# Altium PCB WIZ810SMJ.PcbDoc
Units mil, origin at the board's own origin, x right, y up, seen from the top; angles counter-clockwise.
Board outline 984.25 x 2047.24 mil, 2 copper layers (Top Layer, Bottom Layer); 47 components, 44 nets, 208 pads, 90 vias.
Unrouted connection lines stored in the file: 4.
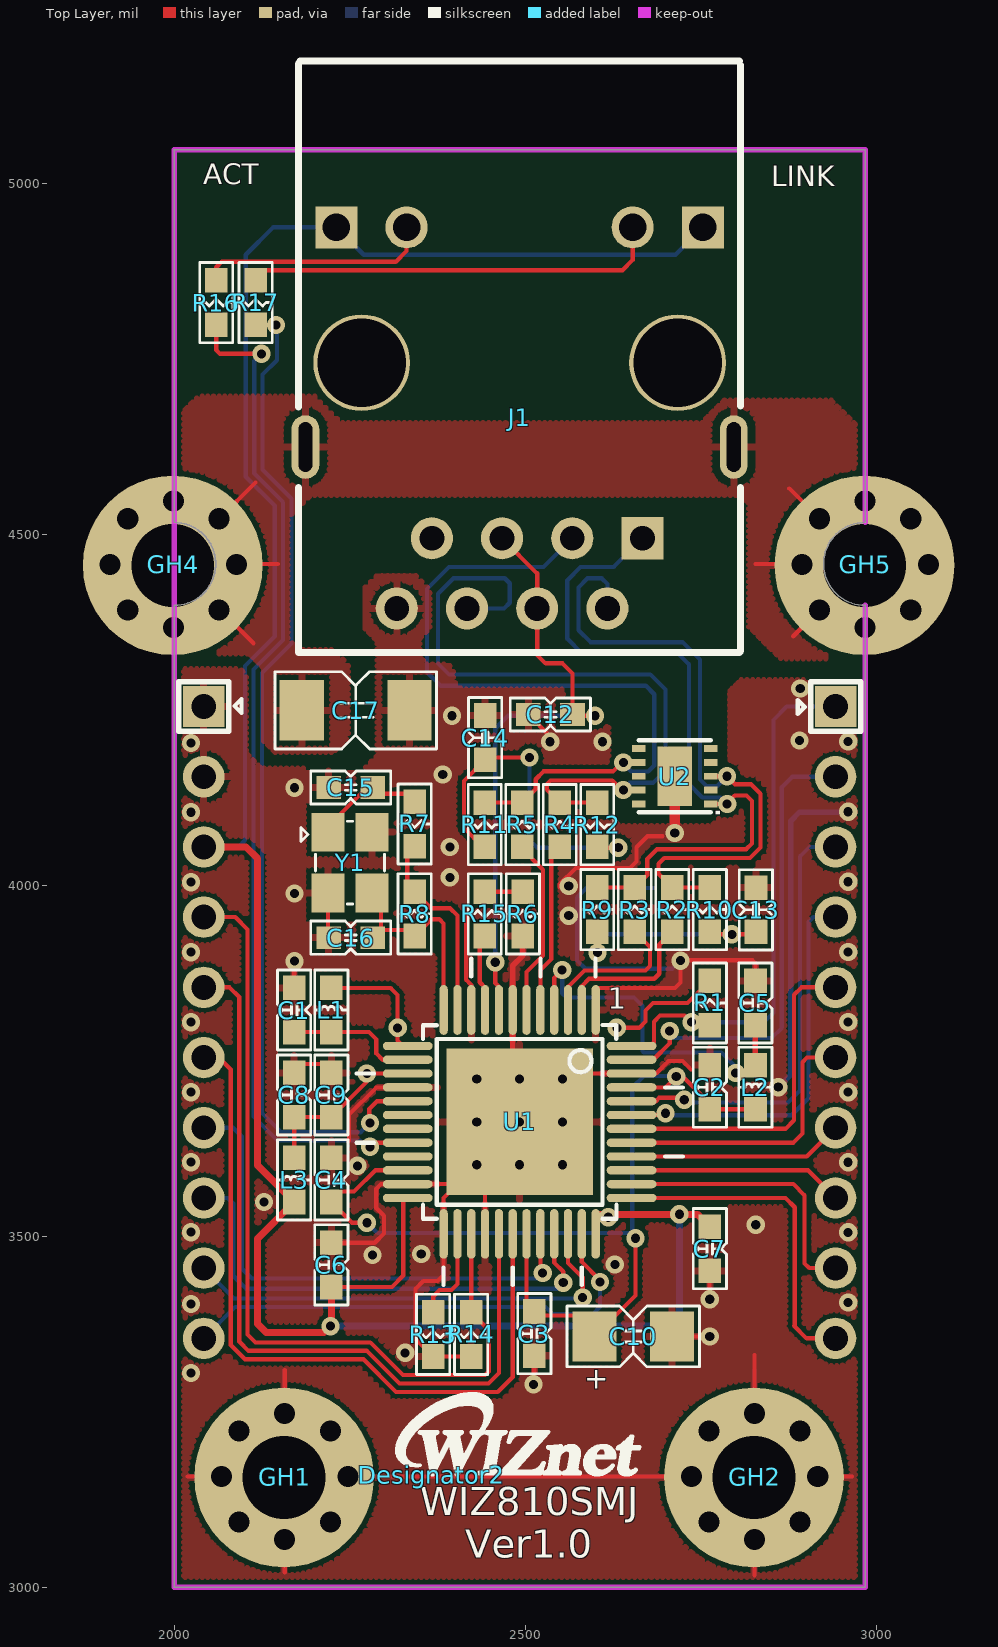
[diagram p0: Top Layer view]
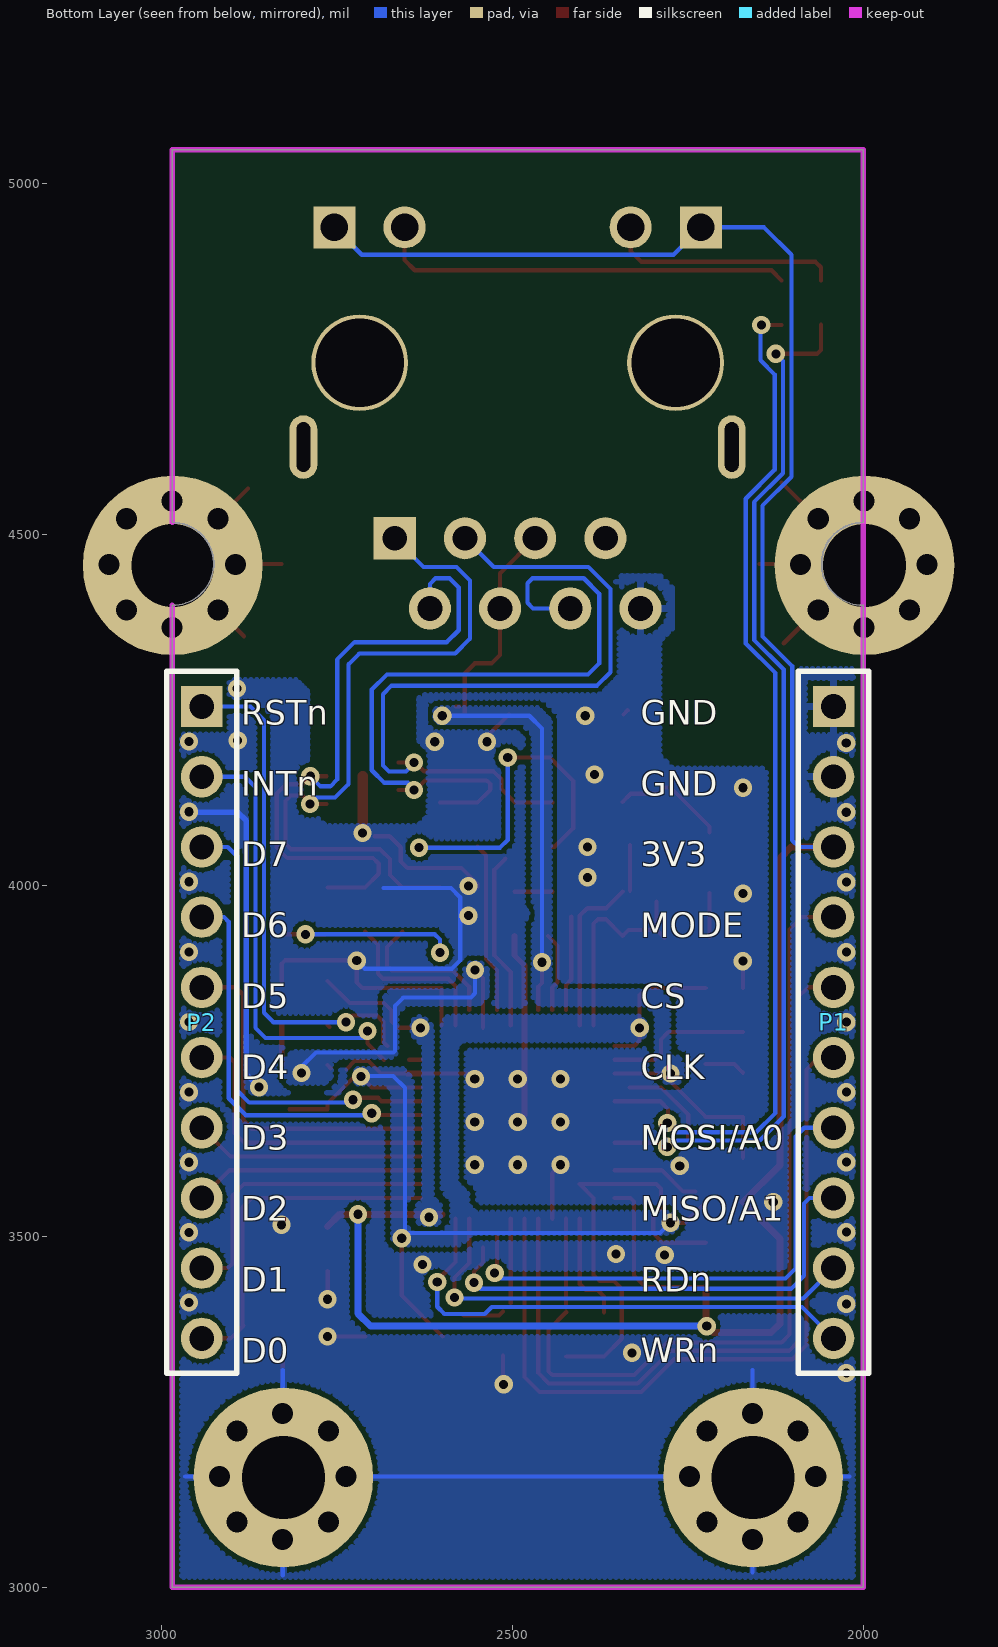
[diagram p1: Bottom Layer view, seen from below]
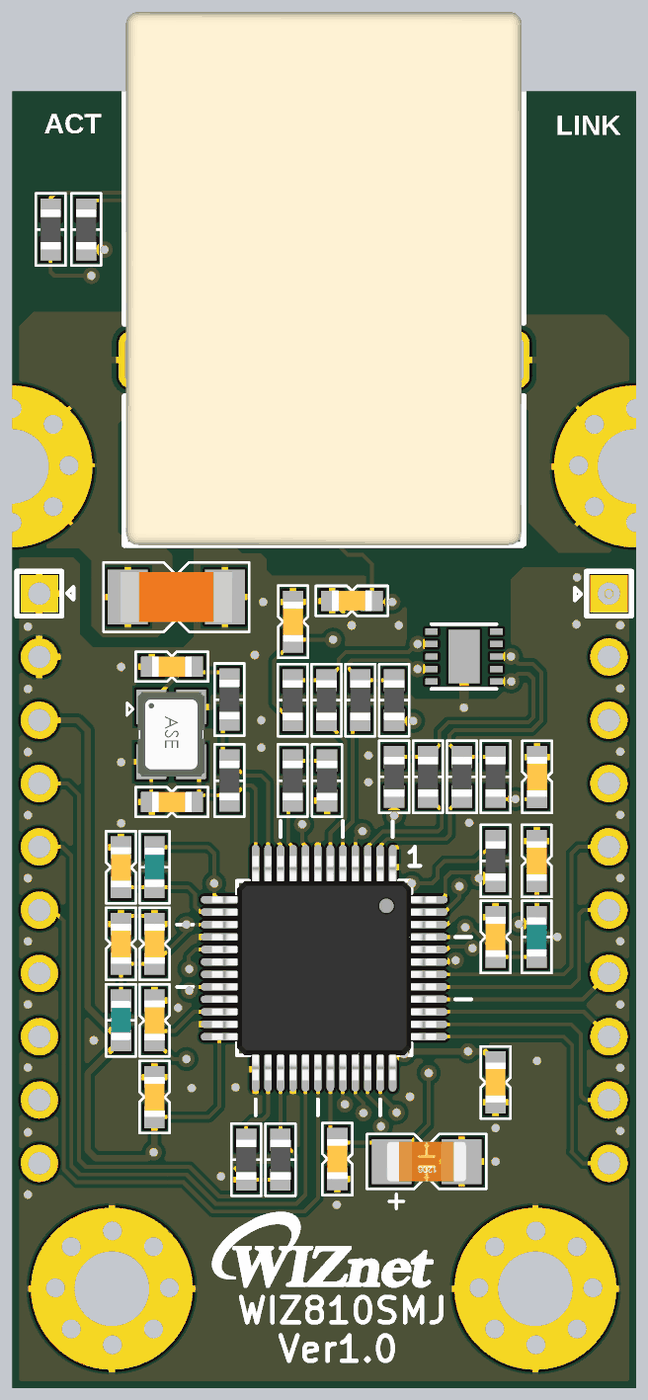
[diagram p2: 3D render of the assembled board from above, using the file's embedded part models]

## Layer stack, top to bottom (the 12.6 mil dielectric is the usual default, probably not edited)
Top Layer: signal copper 1.4
Dielectric: core 12.6, FR-4, Dk 4.8
Bottom Layer: signal copper 1.4

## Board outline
2000,3000 2000,4398.43 ccw(c2000,4457.48) 2000,4516.53 2000,5047.24 2984.25,5047.24 2984.25,4516.53 ccw(c2984.25,4457.48) 2984.25,4398.43 2984.25,3000

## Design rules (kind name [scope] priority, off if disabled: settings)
Clearance [All] p1: gap=6
DiffPairsRouting [All] p1: maxlimit=10 minlimit=10 mostfreqgap=10 maxuncoupledlength=500
FabricationTestPointUsage TestPointUsage [All] p1: valid=0 allowmultiple=FALSE
FabricationTestpoint Testpoint [All] p1: side=3 testpointundercomponent=TRUE minsize=40 maxsize=100 preferedsize=60 minholesize=0 maxholesize=40 preferedholesize=32 testpointgrid=1 allowsidetop=TRUE allowsidebottom=TRUE usegrid=TRUE gridtolerance=0.01
PlaneConnect [All] p1: planeconnectstyle=Relief reliefexpansion=20 reliefentries=4 reliefconductorwidth=10 reliefairgap=6
PolygonConnect PolygonConnect_1 [IsVia] p1: connectstyle=Direct reliefconductorwidth=10 reliefentries=4 polygonreliefangle="90 Angle" airgapwidth=10
PolygonConnect [All] p2: connectstyle=Relief reliefconductorwidth=10 reliefentries=4 polygonreliefangle="90 Angle" airgapwidth=7
RoutingVias [All] p1: holewidth=23.62 width=39.37 viastyle="Through Hole" minholewidth=13 minwidth=26 maxholewidth=28 maxwidth=50
SilkToSolderMaskClearance SilkscreenOverComponentPads [IsPad] p1: minsilkscreentomaskgap=10 clearancetoexposedcopper=TRUE
SolderMaskExpansion [All] p1: expansion=4
Width [All] p1: maxlimit=10 minlimit=6 preferedwidth=6
23 further rules are at their usual default settings.

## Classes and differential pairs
differential pair TXO: +TXO_P -TXO_N
differential pair RXO: +RXO_P -RXO_N

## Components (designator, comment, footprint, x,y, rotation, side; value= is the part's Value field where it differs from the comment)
C1 "100nF" 0603-C 2170.98,3822 r270 top
C2 "100nF" 0603-C 2763,3712 r270 top
C3 "100nF" 0603-C 2513,3361 r90 top
C4 "100nF" 0603-C 2224,3580 r270 top
C5 "100nF" 0603-C 2828,3832 r270 top
C6 "100nF" 0603-C 2224,3459 r270 top
C7 "100nF" 0603-C 2763,3482 r90 top
C8 "100nF" 0603-C 2170.98,3701 r270 top
C9 "100nF" 0603-C 2224,3701 r270 top
C10 "3.3uF/3216" CAP-1206 2654,3357 r180 top
C12 "1uF" 0603-C 2536,4243 r0 top
C13 "100nF" 0603-C 2828.74,3964.76 r270 top
C14 "100nF" 0603-C 2443,4210 r270 top
C15 "8pF" 0603-C 2251.5,4139 r0 top
C16 "8pF" 0603-C 2251.5,3925 r0 top
C17 "1nF/2kV" CAP-1808 2258.58,4248.98 r0 top
Designator2 "Comment" LOGO-WIZNET(SMALL) 2367.13,3160 r0 top
GH1 "CON8" 定位孔（带小孔） 2157.48,3157.48 r0 top
GH2 "CON8" 定位孔（带小孔） 2826.77,3157.48 r0 top locked
GH4 "CON8" 定位孔（带小孔） 1998.87,4456.8 r0 top
GH5 "CON8" 定位孔（带小孔） 2984.25,4456.8 r0 top
J1 "HRW5500RE" RJ-45(HRW5500RE) 2492.13,4744.04 r180 top locked
L1 "HH-1M1608-121JT" 0603-L 2224,3822 r90 top
L2 "HH-1M1608-121JT" 0603-L 2828,3712 r90 top
L3 "HH-1M1608-121JT" 0603-L 2170.98,3580 r90 top
P1 "Header 10" HDR1X10 2042.13,4254.33 r270 bottom locked
P2 "Header 10" HDR1X10 2942.13,4254.33 r270 bottom
R1 "4.7k" 0603-R 2763,3832 r90 top
R2 "3.3R" 0603-R 2709.57,3965 r90 top
R3 "3.3R" 0603-R 2656.14,3965 r90 top
R4 "3.3R" 0603-R 2549.29,4086 r90 top
R5 "3.3R" 0603-R 2495.86,4086 r90 top
R6 "300/1%" RES-0603 2496.65,3959 r90 top
R7 "0R" 0603-R 2342.5,4087 r270 top
R8 "1M" 0603-R 2342.5,3959 r90 top
R9 "49.9R" 0603-R 2602.71,3965 r90 top
R10 "49.9R" 0603-R 2763,3965 r90 top
R11 "49.9R" 0603-R 2442.43,4086 r90 top
R12 "49.9R" 0603-R 2602.71,4086 r90 top
R13 "10K" 0603-R 2369,3360 r90 top
R14 "10K" 0603-R 2423,3360 r90 top
R15 "12K/1%" RES-0603 2442.43,3959 r270 top
R16 "1K" 0603-R 2059.97,4829.76 r90 top
R17 "1K" 0603-R 2116.04,4829.76 r90 top
U1 "W5100S" "WIZNET W5100S QFN&TQFP" 2492.13,3662.6 r270 top locked
U2 "RClamp3304N" DFN-10 2713.08,4155.01 r90 top
Y1 "25MHz" OSC-82J0626 2250.5,4032 r270 top

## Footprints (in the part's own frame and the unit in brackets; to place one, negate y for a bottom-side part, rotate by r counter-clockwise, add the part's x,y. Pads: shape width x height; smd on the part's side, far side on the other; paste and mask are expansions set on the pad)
0603-C [mm]
  rect 0.89x0.82 smd: 1(-0.8,0) 2(0.8,0)
  silkscreen extent -1.45,-0.6 1.45,0.6, body extent -0.93,-0.41 0.93,0.41, height 0.81
0603-L [mm]
  rect 0.89x0.82 smd: 1(-0.8,0) 2(0.8,0)
  silkscreen extent -1.45,-0.6 1.45,0.6, body extent -0.8,-0.4 0.8,0.4, height 0.95
0603-R [mm]
  rect 0.89x0.82 smd: 1(-0.8,0) 2(0.8,0)
  silkscreen extent -1.45,-0.6 1.45,0.6, body extent -0.82,-0.41 0.82,0.41, height 0.46
CAP-1206 [mm]
  rect 1.6x1.8 smd: 1(-1.4,0) 2(1.4,0)
  silkscreen extent -2.4,-1.1 2.4,1.1, body extent -1.6,-0.8 1.6,0.8, height 1
CAP-1808 [mm]
  rect 1.6x2.2 smd: 1(-1.95,0) 2(1.95,0)
  silkscreen extent -2.92,-1.4 2.92,1.4, body extent -2.25,-1.02 2.25,1.01, height 2
DFN-10 [mm] "DFN-10"
  rect 0.25x0.5 smd: 1(-1,-1.3) 2(-0.5,-1.3) 3(0,-1.3) 4(0.5,-1.3) 5(1,-1.3) 6(1,1.3) 7(0.5,1.3) 8(0,1.3) 9(-0.5,1.3) 10(-1,1.3)
  rect 2.15x1.26 smd: 11(0,0)
  silkscreen extent -1.3,-1.3 1.3,1.3
HDR1X10 [mm] "Connector; Header; 10 Position"
  rect 1.5x1.5 hole 0.9: 1(0,0)
  round 1.5 hole 0.9: 2(2.54,0) 3(5.08,0) 4(7.62,0) 5(10.16,0) 6(12.7,0) 7(15.24,0) 8(17.78,0) 9(20.32,0) 10(22.86,0)
  silkscreen extent -1.27,-1.27 24.13,1.27
LOGO-WIZNET(SMALL) [mil]
  silkscreen extent -50,0 296,115
OSC-82J0626 [mm]
  rect 1.4x1.2 smd: 1(-1.1,-0.8) 2(1.1,-0.8) 3(1.1,0.8) 4(-1.1,0.8)
  silkscreen extent -1.5,-1.78 1.5,1.25, body extent -1.7,-1.35 1.7,1.35, height 1.06
RES-0603 [mm]
  rect 0.89x0.82 smd: 1(-0.8,0) 2(0.8,0)
  silkscreen extent -1.45,-0.6 1.45,0.6, body extent -0.82,-0.41 0.82,0.41, height 0.46
RJ-45(HRW5500RE) [mm] "RJ-45(HRW5500RE)"
  rect 1.524x1.524 hole 0.9: 1(-4.445,6.35)
  round 1.524 hole 0.9: 2(-3.175,8.89) 3(-1.905,6.35) 4(-0.635,8.89) 5(0.635,6.35) 6(1.905,8.89) 7(3.175,6.35) 8(4.445,8.89)
  rect 1.524x1.524 hole 1: 9(-6.63,-4.9) 12(6.63,-4.9)
  round 1.524 hole 1: 10(-4.09,-4.9) 11(4.09,-4.9)
  oval 1x2.3 hole 0.5 slot 1.8 at 90 deg: 13(-7.75,3.05) 14(7.75,3.05)
  round 3.5 hole 3.2: ""(-5.715,0) ""(5.715,0)
  silkscreen extent -8,-10.92 8,10.48, body extent -7.92,-10.9 7.96,10.5, height 13.55
"WIZNET W5100S QFN&TQFP" [mm] "WIZNET W5100S QFN&TQFP"
  rect 5.3x5.3 smd: 0(0,0)
  oval 1.8x0.3 smd: 1(-4.05,2.75) 2(-4.05,2.25) 3(-4.05,1.75) 4(-4.05,1.25) 5(-4.05,0.75) 6(-4.05,0.25) 7(-4.05,-0.25) 8(-4.05,-0.75) 9(-4.05,-1.25) 10(-4.05,-1.75) 11(-4.05,-2.25) 12(-4.05,-2.75) 25(4.05,-2.75) 26(4.05,-2.25) 27(4.05,-1.75) 28(4.05,-1.25) 29(4.05,-0.75) 30(4.05,-0.25) 31(4.05,0.25) 32(4.05,0.75) 33(4.05,1.25) 34(4.05,1.75) 35(4.05,2.25) 36(4.05,2.75)
  oval 0.3x1.8 smd: 13(-2.75,-4.05) 14(-2.25,-4.05) 15(-1.75,-4.05) 16(-1.25,-4.05) 17(-0.75,-4.05) 18(-0.25,-4.05) 19(0.25,-4.05) 20(0.75,-4.05) 21(1.25,-4.05) 22(1.75,-4.05) 23(2.25,-4.05) 24(2.75,-4.05) 37(2.75,4.05) 38(2.25,4.05) 39(1.75,4.05) 40(1.25,4.05) 41(0.75,4.05) 42(0.25,4.05) 43(-0.25,4.05) 44(-0.75,4.05) 45(-1.25,4.05) 46(-1.75,4.05) 47(-2.25,4.05) 48(-2.75,4.05)
  silkscreen extent -5.9,-5.9 5.9,5.9, body extent -4.5,-4.5 4.5,4.5, height 1.5
定位孔（带小孔） [mil] "定位孔（带小孔）"
  round 255.91 hole 118.11: 1(-0.86,-1.38)
  round 60 hole 30: 1(0,90) 2(0,-90) 3(-90,0) 4(90,0) 5(-65,65) 6(65,65) 7(-65,-65) 8(65,-65)

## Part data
C1 C2 C3 C4 C5 C6 C7 C8 C9 C12 C13 C14 C15 C16: library part CAP-0603, "Ceramic CAP 0603(1608)"
C10: library part CAP-1206, "Ceramic CAP 1206(3216)"
C17: library part CAP-1808, "Ceramic CAP 1808(4520)"
J1: library part 57-00013QL11-1
L1 L2 L3: library part IND-0603, "Inductor 0603(1608)"
P1 P2: "Header, 10-Pin"
R1 R2 R3 R4 R5 R6 R7 R8 R9 R10 R11 R12 R13 R14 R15 R16 R17: library part RES-0603, "RES0603"
U1: "WIZnet Hardwired TCP/IP Chip"
U2: "Ethernet 3.3V TVS diode, Semtech, SLP2626P10"
Y1: library part OSC-82J0626-25MHz, "X-tal 25MHz,3.2x2.5 SMD, CL=18pF"

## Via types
v1: diameter 26, hole 13, Top Layer to Bottom Layer, tented both sides, 90 vias

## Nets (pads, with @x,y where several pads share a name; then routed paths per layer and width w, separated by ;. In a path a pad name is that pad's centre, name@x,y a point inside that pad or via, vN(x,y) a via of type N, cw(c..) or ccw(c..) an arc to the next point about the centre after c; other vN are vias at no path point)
1V2A: C5.2 L2.2 U1.4 | length 543.8
  Top Layer w6: U1.4@2541.34,3796.73 U1.4@2541.34,3851.61 ; U1.4 2541.34,3867.58 v1(2552.73,3878.97)
  Top Layer w7.87: L2.2 C5.2
  Bottom Layer w6: v1(2552.73,3878.97) 2552.73,3845.9 2558.63,3840 2654.96,3840 2667,3827.96 2667,3763.46 2668.85,3761.61 2779.43,3761.61 2799.82,3741.22 v1(2799.82,3732.2)
1V2D: C2.2 C3.2 C4.2 C10.2 L1.2 L2.1 U1.13 U1.22 U1.31 U1.45 | length 1627.5
  Top Layer w6: C4.2 2253.5,3519 v1(2274.5,3519) v1@2276,3520.5 ; L1.2 2308.41,3853.5 2318.33,3843.58 2318.33,3778.59 2326.05,3770.87 U1.13@2354.33,3770.87 ; C4.2@2238.83,3563.34 2256.34,3563.34 2286.7,3593.7 U1.22@2354.33,3593.7 ; C3.2@2501.97,3404.47 U1.31@2501.97,3524.8 ; C3.2 2518.5,3387 C10.2@2568.88,3387 ; C10.2 2657.22,3415.34 v1(2657.22,3496.87) ; U1.45@2629.92,3711.81 U1.45@2662.09,3711.81 ; U1.45 2699.81,3711.81 v1(2715.18,3727.18) ; v1@2723.75,3728.07 2763,3688.82 C2.2 L2.1@2817,3680.5
  Bottom Layer w6: v1(2274.5,3519) 2289.33,3504.17 2652.6,3504.17 2652.6,3711.28 2669.39,3728.07 v1@2723.75,3728.07
  other v1: 2318.33,3796.62
1V2O: C1.2 L1.1 U1.14 | length 211.2
  Top Layer w6: C1.2 L1.1 2277.5,3790.5 2288,3780 2288,3760.18 2297,3751.18 U1.14@2354.33,3751.18
3V3A: C8.2 C9.2 C12.2 J1.4 J1.5 L3.2 U1.8 U1.15 | length 1168.5
  Top Layer w6: L3.2 C8.2 C9.2 2274.5,3720 v1(2274.5,3731.5) U1.15 U1.15@2354.33,3731.5 ; v1(2457.47,3890.04) 2457.47,3860.5 2462.6,3855.37 U1.8 ; J1.5 2517.13,4444.04 J1.4 2517.13,4327.9 2529.2,4315.84 2553.12,4315.84 2567.5,4301.46 C12.2 ; C12.2@2569.32,4241.18 v1(2599.52,4241.18) ; C12.2@2575.05,4254.39 C12.2@2580.25,4254.39
  Bottom Layer w6: v1(2457.47,3890.04) 2457.47,4223.1 2475.54,4241.18 v1(2599.52,4241.18)
3V3D: C6.2 C7.2 J1.9 J1.12 L3.1 P1.3 R1.2 U1.24 U1.36 | length 3820.2
  Top Layer w6: C6.2 2310.2,3427.5 2326.39,3443.7 2326.39,3549.12 2331.6,3554.33 U1.24@2354.33,3554.33 ; v1(2630.6,3796.62) 2662.52,3796.62 2671.54,3805.64 2671.54,3821.08 2682.28,3831.82 2731.33,3831.82 R1.2
  Top Layer w10: P1.3 2102.45,4054.33 2118.65,4038.12 2118.65,3600.83 L3.1 2118.65,3496.17 2118.65,3375.03 2131.14,3362.54 2213.67,3362.54 v1(2222.76,3371.63) 2224,3372.87 C6.2 ; U1.36@2600,3531 2745.5,3531 C7.2
  Bottom Layer w6: P1.3 2091.58,4054.33 2101.03,4063.78 2101.03,4312.05 2143.21,4354.23 2143.21,4540.43 2101.99,4581.65 2101.99,4897.91 2141.03,4936.95 J1.12 2270.1,4897.95 2714.15,4897.95 J1.9
  Bottom Layer w10: v1(2222.76,3371.63) 2701.87,3371.63 2719.61,3389.36 v1(2719.61,3531.14)
  other v1: 2618.39,3526.89
ACTN: R16.1 U1.20 | length 1517.6
  Top Layer w6: R16.1 2059.97,4762.25 2065.47,4756.75 v1(2124.32,4756.75) ; v1(2278.97,3627.12) 2284.92,3633.07 U1.20 ; U1.20@2299.43,3633.07 U1.20@2354.33,3633.07
  Bottom Layer w6: v1(2124.32,4756.75) 2113.99,4746.42 2113.99,4586.62 2155.21,4545.4 2155.21,4349.26 2113.03,4307.08 2113.03,3670.23 2147.26,3636 2264.85,3636 v1@2273.73,3627.12
CHGND: C17.1 GH4.1 GH4.2 GH4.3 GH4.4 GH4.5 GH4.6 GH4.7 GH4.8 GH5.1 GH5.2 GH5.3 GH5.4 GH5.5 GH5.6 GH5.7 GH5.8 J1.13 J1.14 | length 377.3
  Top Layer w6: GH4.8@2065,4392.48 2113.06,4344.42 ; GH4.6@2065,4522.48 2116.04,4573.52 ; GH4.4@2090,4457.48 2147.51,4457.48 ; 2828.3,4457.48 GH5.1@2894.25,4457.48 ; 2876.3,4564.75 GH5.5 ; 2881.83,4354.38 GH5.7
CSN: P1.5 U1.29 | length 1167.9
  Top Layer w6: P1.5 2078.67,3854.33 2092.65,3840.35 2092.65,3349.63 2105.74,3336.54 2274.49,3336.54 2321.05,3289.98 2447.84,3289.98 2462.6,3304.74 U1.29@2462.6,3524.8
D0: P2.10 U1.37 | length 494.9
  Top Layer w6: U1.37@2629.92,3554.33 2870.67,3554.33 2884,3541 2884,3372.33 ; 2883,3372.33 2901,3354.33 P2.10
D1: P2.9 U1.38 | length 418.6
  Top Layer w6: U1.38@2629.92,3574.02 2882.02,3574.02 2898,3558.03 2898,3461 2904.67,3454.33 P2.9
D2: P2.8 U1.39 | length 328.5
  Top Layer w6: U1.39@2629.92,3593.7 2902.76,3593.7 P2.8
D3: P2.7 U1.40 | length 329.2
  Top Layer w6: U1.40@2629.92,3613.39 2901.18,3613.39 P2.7
D4: P2.6 U1.41 | length 421.9
  Top Layer w6: U1.41@2629.92,3633.07 2881.99,3633.07 2895,3646.08 2895,3747.66 2901.67,3754.33 P2.6
D5: P2.5 U1.42 | length 500.5
  Top Layer w6: U1.42@2629.92,3652.76 2870.84,3652.76 2883,3664.92 2883,3843.75 2893.58,3854.33 P2.5
D6: P2.4 U1.43 | length 607.1
  Top Layer w6: U1.43@2629.92,3672.44 U1.43@2683.71,3672.44 ; U1.43 v1@2697.46,3672.44
  Bottom Layer w6: v1(2699.91,3674.89) 2702.68,3672.12 2879.32,3672.12 2903.6,3696.4 2903.6,3947.6 2910.33,3954.33 P2.4
D7: P2.3 U1.44 | length 663.4
  Top Layer w6: U1.44@2629.92,3692.13 U1.44@2651.68,3692.13 ; U1.44 2686.03,3692.12 2690.8,3696.89 2723.82,3696.89 v1(2726.59,3694.12)
  Bottom Layer w6: v1(2726.59,3694.12) 2730.56,3690.16 2874.54,3690.16 2891.6,3707.21 2891.6,4040.93 2905,4054.33 P2.3
GND: C1.1 C2.1 C3.1 C4.1 C5.1 C6.1 C7.1 C8.1 C9.1 C10.1 C12.1 C13.1 C14.1 C15.1 C16.1 C17.2 GH1.1 GH1.2 GH1.3 GH1.4 GH1.5 GH1.6 GH1.7 GH1.8 GH2.1 GH2.2 GH2.3 GH2.4 GH2.5 GH2.6 GH2.7 GH2.8 J1.8 P1.1 P1.2 R6.1 R13.1 R14.1 U1.0 U1.1 U1.7 U1.10 U1.16 U1.23 U1.25 U1.28 U1.46 U2.11 Y1.2 Y1.4 | length 6327.8
  Top Layer w6: 2019.42,3157.48 GH1.3 GH1.1@2157.48,3157.48 ; 2157.48,3021.07 GH1.2 GH1.1@2157.48,3157.48 ; 2157.48,3309.02 2157.48,3247.48 GH1.1@2157.48,3157.48 ; C8.1 2183.49,3745 C9.1@2224,3745 ; C1.1 v1@2170.98,3887.49 ; C16.1@2219.01,3926 Y1.2 ; C6.1 2285.79,3490.5 2298.79,3503.5 2298.79,3528.91 2288,3539.69 2288,3567.34 2294.68,3574.02 2403.54,3574.02 2383.86,3554.33 U1.25@2383.86,3524.8 ; 2249.14,3635.84 2249.14,3672.95 2288,3711.81 U1.16 ; C17.2 C17.2@2341.33,4243 ; U1.25@2383.86,3498.23 2383.86,3444.72 2375,3435.86 2354.86,3435.86 2343.86,3424.86 2343.86,3353.65 R13.1 R14.1 ; U1.25@2384,3498.37 U1.25@2384,3532 ; 2415.73,3955.02 2415.73,3865.25 2423.23,3857.74 U1.10 ; v1(2431.02,3601.5) 2442.91,3589.61 U1.28@2442.91,3524.8 ; U1.7@2482.28,3800.39 U1.7@2482.28,3838.61 ; C12.1 2535.58,4211.92 v1(2535.58,4204.2) ; v1@2513.05,3296.69 C3.1@2513.05,3329.45 ; 2549.29,3996.5 2549.29,4001.38 2572.3,4024.4 2649.39,4024.4 2658.6,4033.6 2658.6,4053.79 2674.36,4069.55 2695.83,4069.55 ; U1.0@2561.02,3731.5 U1.46@2629.92,3731.5 ; U1.1@2600.39,3800.39 2600.39,3820.11 U1.1@2601.36,3821.08 ; U1.1 2600.4,3853.45 2713.39,3853.45 2721.26,3861.32 v1(2721.26,3892.3) ; U1.46 2686.66,3731.49 2704.35,3749.18 2724.29,3749.18 2736.04,3737.43 ; C10.1@2709.33,3356.78 v1@2755.14,3356.78 ; v1@2710.8,4070.34 v1@2718.97,4078.51 ; v1@2721.26,3892.75 2823.7,3892.75 2828,3888.45 C5.1 ; C2.1@2758.46,3738.96 C2.1 ; v1@2762.72,3419.59 C7.1@2762.72,3450.22 ; 2826.77,3016.71 GH2.1@2826.77,3157.48 ; 2826.77,3330.71 GH2.1@2826.77,3157.48 ; C5.1@2828.41,3862.77 C5.1@2828.41,3863.5 ; 2965.72,3157.48 GH2.4 GH2.1@2826.77,3157.48 ; GH1.1@2157.48,3157.48 GH1.4 GH2.3 GH2.1@2826.77,3157.48
  Top Layer w8: U1.0@2482.28,3672.44 U1.7 2482.28,3885.4 2496.65,3899.77 R6.1 ; U1.46@2629.92,3731.5 2649.24,3731.5 U1.46@2650.41,3732.66
  Top Layer w15: v1(2713.08,4074.12) U2.11
  Bottom Layer w6: 2019.42,3157.48 GH1.3 GH1.1@2157.48,3157.48 ; 2157.48,3021.07 GH1.2 GH1.1@2157.48,3157.48 ; 2157.48,3309.02 GH1.1@2157.48,3157.48 ; 2683.13,3995.79 2587.14,3995.79 2573.96,3982.61 2573.96,3892.62 2585.66,3880.92 2709.89,3880.92 v1(2721.26,3892.3) ; 2826.77,3016.71 GH2.1@2826.77,3157.48 ; 2826.77,3309.02 GH2.1@2826.77,3157.48 ; 2965.72,3157.48 GH2.4 GH2.1@2826.77,3157.48 ; GH1.1@2157.48,3157.48 GH1.4 GH2.3 GH2.1@2826.77,3157.48
  Bottom Layer w8: v1(2860.51,3712.16) 2878.6,3730.25 2878.6,4091.54 2890.94,4103.88 v1@2961.21,4103.88
  other v1: 2512,3288.78 2023.89,3304.94 2329.06,3333.65 2763,3357.02 2023.89,3403.23 2960.08,3405.44 2763,3410 2627.73,3459.52 2282.66,3473.14 2352.06,3474.42 2960.08,3505.31 2023.89,3505.53 2828.41,3516.12 2128,3548.5 2261.23,3600.06 2492.13,3601.5 2553.23,3601.5 2023.89,3605.26 2960.08,3605.17 2431.02,3662.6 2492.13,3662.6 2553.23,3662.6 2023.89,3704.99 2960.08,3705.04 2431.02,3723.7 2492.13,3723.7 2553.23,3723.7 2023.89,3804.72 2960.08,3804.9 2171.32,3891.58 2023.89,3904.45 2960.08,3904.77 2562.11,3956.46 2171.26,3988.03 2562.11,3998.72 2023.89,4004.18 2960.08,4004.63 2392.74,4010.95 2392.74,4054.33 2024,4103.77 2960.08,4104.5 2171.26,4138.62 2382.53,4157.45 2024,4202.19 2610.12,4204.2 2960.08,4204.37 2890.91,4205.81 2395.86,4241.18 2891.77,4280
INTN: P2.2 U1.47 | length 655.6
  Top Layer w6: U1.47@2629.92,3751.18 U1.47@2646.65,3751.18 ; U1.47@2682.5,3751.18 2705.84,3774.52 v1(2705.84,3792.01)
  Bottom Layer w6: v1@2708.67,3782.13 2851.11,3782.13 2865.6,3796.62 2865.6,4139.33 2880.6,4154.33 P2.2
LINKN: R17.1 U1.17 | length 1503.5
  Top Layer w6: R17.1@2116.43,4797.88 v1(2144.91,4797.88) ; v1@2277.97,3653.12 2277.97,3681.12 2288.97,3692.12 U1.17 ; U1.17@2303.43,3692.13 U1.17@2354.33,3692.13
  Bottom Layer w6: v1(2144.91,4797.88) 2146.32,4796.47 2146.32,4747.64 2125.99,4727.31 2125.99,4591.59 2167.21,4550.37 2167.21,4344.29 2125.03,4302.11 2125.03,3675.21 2152.23,3648 2265.85,3648 v1(2278.97,3661.12)
MISO/A1: P1.8 U1.33 | length 657.6
  Top Layer w6: U1.33@2541.34,3483.89 2541.34,3462.21 2554.26,3449.29 v1(2554.26,3433.63)
  Bottom Layer w6: P1.8@2069.9,3554.33 2076.4,3554.33 2084.26,3546.47 2084.26,3443.42 2102.83,3424.85 2545.47,3424.85 v1(2554.26,3433.63)
MODE1: R13.2 U1.26 | length 157.6
  Top Layer w6: R13.2 2369,3414 2378,3423 2395,3423 2403.54,3431.54 U1.26@2403.54,3524.8
MODE2: P1.4 R14.2 U1.27 | length 1237.6
  Top Layer w6: P1.4 2087,3954.33 2104.65,3936.68 2104.65,3359.68 2115.8,3348.54 2279.46,3348.54 2326.02,3301.98 2442.87,3301.98 2448.14,3307.26 2448.14,3366.35 R14.2 ; R14.2@2423.23,3398.27 U1.27@2423.23,3524.8
MOSI/A0: P1.7 U1.32 | length 702.9
  Top Layer w6: v1@2521.65,3456 U1.32
  Bottom Layer w6: P1.7@2071.51,3654.33 2083.84,3654.33 2096.26,3641.91 2096.26,3454.01 2110.71,3439.57 2516.91,3439.57 v1(2524.89,3447.55)
NetC13_2: C13.2 R9.1 R10.1 | length 272.1
  Top Layer w6: R10.1@2766.67,3929.83 v1(2794.45,3929.83) C13.2@2825.31,3929.83
  Bottom Layer w6: v1(2602.87,3903.67) 2602.87,3922.61 2610.1,3929.83 v1(2794.45,3929.83)
NetC14_2: C14.2 R11.1 R12.1 | length 486.8
  Top Layer w6: C14.2@2442.3,4177.8 2412.83,4148.34 2412.83,4081.07 2439.4,4054.5 R11.1 ; C14.2@2446.19,4181.69 v1(2506.23,4181.69) ; R12.1@2603.98,4053.24 v1(2632.66,4053.24)
  Bottom Layer w6: v1(2506.23,4181.69) 2506.23,4064.14 2517.13,4053.24 v1(2632.66,4053.24)
NetC15_2: C15.2 R7.1 Y1.1 | length 150.4
  Top Layer w6: Y1.1 2219.01,4083.5 2274.5,4139 C15.2 ; C15.2@2292,4130 2331,4130 R7.1
NetC16_2: C16.2 R8.1 U1.12 Y1.3 | length 306.4
  Top Layer w6: C16.2 C16.2@2294,3936 ; Y1.3@2294.5,3976.19 2294.5,3936.5 C16.2@2294,3936 ; U1.12@2383.86,3800.39 2383.86,3945.14 2377.75,3951.25 2366.25,3951.25 R8.1 2334.01,3936 C16.2@2294,3936
NetJ1_10: J1.10 R17.2 | length 595.8
  Top Layer w6: R17.2 2130.56,4875.78 2638.63,4875.78 2653.15,4890.3 J1.10
NetJ1_11: J1.11 R16.2 | length 333.2
  Top Layer w6: R16.2 2059.97,4880.08 2067.67,4887.78 2315.62,4887.78 2331.1,4903.26 J1.11
NetR2_1: R2.1 U1.2 | length 240.9
  Top Layer w6: U1.2@2580.71,3800.39 U1.2 2580.71,3856.15 2591.04,3866.48 2683.86,3866.48 2691,3873.62 2691,3914.93 R2.1
NetR3_1: R3.1 U1.3 | length 252.9
  Top Layer w6: U1.3 U1.3@2561.02,3855 ; U1.3 2561.03,3855 2584.51,3878.48 2671.54,3878.48 2678,3884.94 2678,3911.65 R3.1
NetR4_1: R4.1 U1.5 | length 243.9
  Top Layer w6: U1.5 2521.65,3879.01 2537.29,3894.64 2537.29,4042.5 R4.1
NetR5_1: R5.1 U1.6 | length 274.8
  Top Layer w6: R5.1@2509.65,4037.42 2525.29,4021.79 2525.29,3899.61 2501.97,3876.29 U1.6 ; U1.6 2501.97,3800.39 U1.6
NetR6_2: R6.2 R15.1 | length 54.2
  Top Layer w6: R15.1 R6.2
NetR7_2: R7.2 R8.2 U1.11 | length 296.2
  Top Layer w6: R8.2@2332,3992 R7.2@2332,4057.01 ; R8.2 2366,3967 2393,3967 2403.54,3956.46 U1.11@2403.54,3800.39
NetR15_2: R15.2 U1.9 | length 114.3
  Top Layer w6: U1.9 2442.91,3853.87 2435.23,3861.56 2435.23,3913.73 R15.2@2449,3927.5
RDN: P1.9 U1.34 | length 715.2
  Top Layer w6: P1.9 P1.9@2067.67,3454.33 ; U1.34@2561.02,3492.64 U1.34@2561.02,3524.8 ; U1.34 2561.02,3461.65 2581.89,3440.78 v1(2581.89,3412.57)
  Bottom Layer w6: P1.9 2085.34,3411.12 2580.44,3411.12 v1(2581.89,3412.57)
RSTN: P2.1 R1.1 U1.48 | length 737.3
  Top Layer w6: U1.48@2677.78,3770.86 2683.54,3776.63 2683.54,3805.28 2692.27,3814.01 2727.48,3814.01 v1(2736.77,3804.72) ; R1.1@2760.3,3797.8 R1.1
  Bottom Layer w6: v1(2736.77,3804.72) 2840.18,3804.72 2853.6,3818.14 2853.6,4235.29 2872.64,4254.33 v1(2942.13,4254.33)
RXO_N: J1.6 R4.2 R12.2 U2.9 | length 1059.7
  Top Layer w6: R12.2 R4.2 2531,4135.78 2531,4144.08 2536.04,4149.12 2624.12,4149.12 ; 2624.12,4149.01 v1@2637.98,4135.15 ; v1@2638.16,4135.32 U2.9
  Bottom Layer w6: J1.6 2470.04,4394.04 2478.13,4402.13 2478.13,4429.87 2471,4437 2398,4437 2376,4415 2376,4315.74 2391.72,4300.02 2678.33,4300.02 2699.95,4278.4 2699.95,4163.56 2682.02,4145.63 2648.46,4145.63 v1@2637.98,4135.15
  other v1: 2639.9,4135.32
RXO_P: J1.3 R5.2 R11.2 U2.7 | length 1100.5
  Top Layer w6: R11.2 R5.2 2515,4136.64 2515,4150.71 2526.29,4162 2625.18,4162 ; 2625.18,4161.89 2637.98,4174.69 U2.7
  Bottom Layer w6: J1.3 2526.09,4453 2391.37,4453 2360,4421.63 2360,4303.16 2379.14,4284.02 2671.7,4284.02 2683.95,4271.77 2683.95,4170.19 2675.39,4161.63 2651.05,4161.63 v1@2637.98,4174.69
  other v1: 2639.9,4174.69
SCLK: P1.6 U1.30 | length 1101.8
  Top Layer w6: P1.6 2063.67,3754.33 2080.65,3737.35 2080.65,3344.66 2100.77,3324.54 2269.52,3324.54 2316.07,3277.98 2460.98,3277.98 2482.28,3299.28 U1.30@2482.28,3524.8
TXO_N: J1.2 R2.2 R10.2 U2.3 | length 975
  Top Layer w6: R10.2 R2.2 2690,4016.07 2690,4030.37 2698.15,4038.52 2820.41,4038.52 2835.39,4053.5 2835.39,4129.99 2821.72,4143.66 ; U2.3 v1(2787.36,4155.01) 2798.82,4143.55 2821.72,4143.55
  Bottom Layer w6: J1.2@2609,4402.17 J1.2 2617.13,4428.87 2609,4437 2589,4437 2576,4424 2576,4363 2593,4346 2724.24,4346 2749.2,4321.05 2749.2,4150.38 2758.93,4140.64 2772.99,4140.64 v1(2787.36,4155.01)
TXO_P: J1.1 R3.2 R9.2 U2.1 | length 1027.5
  Top Layer w6: R9.2 R3.2 2674,4014.35 2674,4037 2688,4051 2814.79,4051 2822.97,4059.18 2822.97,4119.79 2815.21,4127.55 2798.6,4127.55 2787.73,4116.68 v1(2787.73,4115.64) ; U2.1 2786.69,4115.64 v1@2787.21,4116.16
  Bottom Layer w6: J1.1 2626.09,4453 2579,4453 2560,4434 2560,4351 2581,4330 2717.62,4330 2733.2,4314.42 2733.2,4143.75 2752.3,4124.64 2778.73,4124.64 v1(2787.73,4115.64)
WRN: P1.10 U1.35 | length 727.7
  Top Layer w6: U1.35@2580.71,3524.8 2580.71,3463.03 2606.62,3437.11 v1(2606.62,3434.41)
  Bottom Layer w6: P1.10 2086.92,3399.12 2528.9,3399.12 2538.9,3389.12 2596.51,3389.12 2606.62,3399.24 v1(2606.62,3434.41)
pads on no net: J1. J1.7 U1.18 U1.19 U1.21 U2.2 U2.4 U2.5 U2.6 U2.8 U2.10
copper on no net:
  other v1: 2023.89,3304.94 2717.13,4744.04

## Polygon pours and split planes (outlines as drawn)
CHGND on Top Layer "Mid-Layer 2-No Net" (hatched 90Degree grid 0 track 8, remove dead copper, pour order 17): 2985.01,4322.75 2864.07,4322.75 2826.82,4360 2818.82,4368 2818.82,4544 2807.5,4555.32 2760,4555.32 2194.09,4555.32 2162.01,4523.24 2162.01,4350.65 2177.71,4334.95 2226.89,4334.95 2240,4321.85 2248,4313.85 2248,4210.65 2226.57,4189.22 2216,4189.22 2144,4189.22 2128,4205.22 2128,4308.52 2106.97,4329.55 2080,4329.55 2000,4329.55 2000,4661.32 2034.68,4696 2200,4696 2232,4664 2237.46,4658.54 2264,4658.54 2751.78,4658.54 2784,4690.76 2935.55,4690.76 2960,4666.31 2983.65,4642.66 2983.65,4625.66
GND on Top Layer "Mid-Layer 2-No Net" (hatched 90Degree grid 0 track 8, remove dead copper, pour order 13): 2985.52,4292.09 2807.42,4292.09 2791.23,4275.9 2791.23,4109.85 2773.92,4092.54 2765.62,4084.24 2704,4084.24 2634.22,4084.24 2619.16,4099.3 2619.16,4263.1 2603.34,4278.91 2409.09,4278.91 2397.69,4290.31 2397.69,4306.82 2390.03,4314.48 2360,4314.48 2352,4322.48 2350,4324.48 2350,4351.45 2364.08,4365.53 2364.08,4368 2364.08,4420.4 2343.86,4440.63 2289.09,4440.63 2272.46,4424 2272,4423.54 2272,4365.33 2289.71,4347.62 2289.71,4336 2289.71,4184.52 2271.35,4166.16 2124.16,4166.16 2102.45,4187.88 2102.45,4299.29 2094.02,4307.71 1999.57,4307.71 1998.63,4306.77 1998.63,3001.37 2000,3000 2984.25,3000
GND on Bottom Layer "Mid-Layer 2-No Net" (hatched 90Degree grid 0 track 8, remove dead copper, pour order 15): 2611.23,4271.02 2627.76,4271.02 2632.66,4266.12 2632.66,4205.5 2619.16,4192 2616.64,4189.48 2592,4189.48
GND on Bottom Layer "Mid-Layer 2-No Net" (hatched 90Degree grid 0 track 8, remove dead copper, pour order 12): 2985.52,4292.09 2807.42,4292.09 2791.23,4275.9 2791.23,4109.85 2773.92,4092.54 2765.62,4084.24 2704,4084.24 2634.22,4084.24 2619.16,4099.3 2619.16,4263.1 2603.34,4278.91 2409.09,4278.91 2397.69,4290.31 2397.69,4306.82 2390.03,4314.48 2360,4314.48 2352,4322.48 2350,4324.48 2350,4351.45 2364.08,4365.53 2364.08,4368 2364.08,4420.4 2343.86,4440.63 2289.09,4440.63 2272.46,4424 2272,4423.54 2272,4365.33 2289.71,4347.62 2289.71,4336 2289.71,4184.52 2271.35,4166.16 2124.16,4166.16 2102.45,4187.88 2102.45,4299.29 2094.02,4307.71 1999.57,4307.71 1998.63,4306.77 1998.63,3001.37 2000,3000 2984.25,3000
3V3A on Bottom Layer "Mid-Layer 2-No Net" (hatched 90Degree grid 0 track 8, remove dead copper, pour order 11): 2256.86,3744.69 2256.86,3725.71 2263.53,3719.04 2281.03,3719.04 2288,3726.01 2294.63,3732.63 2294.63,3815.65 2308.68,3829.7 2333.8,3829.7 2459.74,3829.7 2470.04,3840 2470.04,4213.8 2483.28,4227.04 2488.2,4231.96 2604.66,4231.96 2609.76,4237.06 2609.76,4249.35 2606.95,4252.16 2575.33,4252.16 2463.61,4252.16 2451.84,4240.39 2446.04,4234.6 2446.04,3905.24 2446.04,3863.08 2437.96,3855 2431.99,3849.03 2350.13,3849.03 2289.18,3849.03 2277.24,3837.08 2277.24,3759.9 2271.67,3754.33 2263.34,3754.33 2257.03,3748.02
1V2D on Bottom Layer "Mid-Layer 2-No Net" (hatched 90Degree grid 0 track 8, remove dead copper, pour order 10): 2328,3778.41 2319.24,3778.41 2309.57,3788.08 2309.57,3802.92 2320,3813.36 2590.71,3813.36 2599.52,3804.55 2599.52,3564.66 2586.86,3552 2585.85,3551 2585.85,3528 2585.85,3518.65 2601.33,3503.17 2640.17,3503.17 2652.99,3515.99 2652.99,3547 2642.13,3557.86 2642.13,3724.08 2656.1,3738.04 2704,3738.04 2720,3738.04 2723.75,3734.29 2723.75,3720.77 2720,3717.02 2680,3717.02 2674.98,3712 2670.09,3707.11 2670.09,3688 2670.09,3496.34 2661.76,3488 2573.02,3488 2556.84,3504.17 2528,3504.17 2273.78,3504.17 2265.95,3512 2264.15,3513.8 2264.15,3521.66 2276.03,3533.54 2352,3533.54 2552,3533.54 2562.46,3544 2563.13,3544.67 2563.13,3560 2579,3575.87 2579,3584 2579,3770.74 2571.33,3778.41 2328,3778.41
3V3D on Bottom Layer "Mid-Layer 2-No Net" (hatched 90Degree grid 0 track 8, remove dead copper, pour order 18): 2628.01,3812.66 2613.69,3798.33 2613.69,3792 2613.69,3555.51 2602.35,3544.17 2602.35,3521.93 2609.59,3514.7 2628.55,3514.7 2636.56,3522.7 2636.56,3541.7 2626.09,3552.17 2626.09,3770.74 2642.13,3786.79 2642.13,3805.81 2635.34,3812.6
1V2A on Bottom Layer "Mid-Layer 2-No Net" (hatched 90Degree grid 0 track 8, remove dead copper, pour order 14): 2544.55,3889.01 2559.29,3889.01 2567.29,3881.01 2567.29,3862.3 2575.29,3854.3 2580.58,3849.01 2660.98,3849.01 2673.03,3849.01 2681.03,3841.01 2681.03,3817.01 2681.03,3773.23 2689.92,3764.34 2691.64,3762.62 2719.29,3762.62 2812.19,3762.62 2823.29,3751.52 2823.29,3725.56 2815.29,3717.56 2767.24,3717.56 2761.69,3723.11 2757.65,3727.14 2757.65,3736.08 2757.65,3745.01 2747.83,3754.84 2695.29,3754.84 2670.79,3754.84 2664.52,3761.11 2664.52,3816.32 2655.83,3825.01 2650.52,3830.32 2551.29,3830.32 2547.47,3830.32 2535.29,3842.5 2535.29,3879.75
1V2D on Bottom Layer "Mid-Layer 2-No Net" (hatched 90Degree grid 0 track 8, remove dead copper, pour order 16): 2670.09,3568 2670.09,3707.11 2680,3717.02 2720,3717.02 2723.75,3720.77 2723.75,3734.29 2720,3738.04 2656.1,3738.04 2648,3729.94 2642.13,3724.08 2642.13,3560 2650.13,3552 2669.76,3552

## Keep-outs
Keep-Out Layer:
  lines w7.87: 2000,4309.45 2000,5047.24 2350,5047.24 2984.25,5047.24 2984.25,4516.53 ; 2000,4398.43 2000,3000 2984.25,3000 2984.25,4398.43

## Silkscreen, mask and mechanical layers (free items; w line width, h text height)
Top Overlay:
  lines w6: 2086.06,4255.02 2095.89,4245.19 2095.89,4264.86 2086.06,4255.02 ; 2888.36,4243.81 2898.19,4253.64 2888.36,4263.47 2888.36,4243.81
  lines w8: 2006.42,4219.08 2077.61,4219.08 2077.61,4289.63 2006.42,4289.63 2006.42,4219.08 ; 2906.65,4219.03 2977.83,4219.03 2977.83,4289.58 2906.65,4289.58 2906.65,4219.03
  text "ACT" at 2041.52,4988.16 h50
  text "LINK" at 2850.37,4985.66 h50
  text "+" at 2584.51,3282.41 h30
  text "WIZ810SMJ" at 2350.6,3102.61 h40
  text "Ver1.0" at 2414.88,3042.01 h40
Bottom Overlay:
  text "GND" at 2317,4216.2 h60
  text "RSTn" at 2885.88,4216.2 h60
  text "GND" at 2317,4115.27 h60
  text "INTn" at 2885.88,4115.27 h60
  text "3V3" at 2317,4014.34 h60
  text "D7" at 2885.88,4014.34 h60
  text "MODE" at 2317,3913.41 h60
  text "D6" at 2885.88,3913.41 h60
  text "CS" at 2317,3812.49 h60
  text "D5" at 2885.88,3812.49 h60
  text "CLK" at 2317,3711.56 h60
  text "D4" at 2885.88,3711.56 h60
  text "MOSI/A0" at 2317,3610.63 h60
  text "D3" at 2885.88,3610.63 h60
  text "MISO/A1" at 2317,3509.7 h60
  text "D2" at 2885.88,3509.7 h60
  text "RDn" at 2317,3408.77 h60
  text "D1" at 2885.88,3408.77 h60
  text "WRn" at 2317,3307.85 h60
  text "D0" at 2885.88,3307.47 h60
